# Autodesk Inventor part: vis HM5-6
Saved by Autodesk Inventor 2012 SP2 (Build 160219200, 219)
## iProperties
Created: 2013-04
Part Number: vis HM5-6
Material: Default
Document SubType Name: Modeling
Designer: papa
Density: 1 g/cm^3
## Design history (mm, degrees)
node "vis HM5-61"
node "vis HM5-6"
node "Base1"
